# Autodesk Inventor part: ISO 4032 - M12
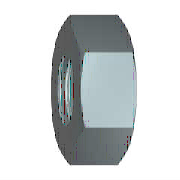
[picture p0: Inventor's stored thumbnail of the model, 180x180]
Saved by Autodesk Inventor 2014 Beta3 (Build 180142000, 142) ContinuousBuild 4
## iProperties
IsCustomPart: 0
Created: 2010-02
Part Number: ISO 4032 - M12
Material: Stainless Steel, 440C
Description: Hexagon nuts, style 1 - Product grades A and B
Document SubType Name: Modeling
Standard: ISO 4032
Designer: Thom Tremblay
Standard Revision: Third edition 1999-08-15
Standards Organization: ISO
Language: en-US
Size Designation: M12
Categories: <MemberInstance><Categories><Category DisplayName="Fasteners" InternalName="e4da775c-781d-43d5-af7c-5136215cf5a6" Mnemonic="FSTN"><Category DisplayName="Nuts" I
Density: 7.75 g/cm^3
Appearance: Steel
Author: Thom Tremblay
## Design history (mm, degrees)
sketch "Sketch1"
  geometry: L1 (-10.392, 0)-(-5.196, 9); L2 (-5.196, 9)-(5.196, 9); L3 (5.196, 9)-(10.392, 0); L4 (10.392, 0)-(5.196, -9); L5 (5.196, -9)-(-5.196, -9); L6 (-5.196, -9)-(-10.392, 0); 2 further points
  constraints: 12 end point, 1 coincident, 1 horizontal, 11 other
  dimensions: "d0" = 20.78461 distance of L3.end L1.start (= 1.1547 x SW)
extrude "Body" new body sketch "Sketch1" distance "d1" = 10.8 (= KOH); taper "d2" = 0 deg
sketch "Sketch2"
  geometry: L1 (0, 5.196)-(0, 10.392) reference; L2 (0, 10.392)-(10.8, 10.392) reference; L3 (10.8, 5.196)-(10.8, 10.392) reference; L4 (-2.16, 0)-(12.96, 0) reference; L5 (1.208, 10.392)-(0, 8.3); L6 (9.592, 10.392)-(10.8, 8.3)
  constraints: 4 end point, 4 point on line
  dimensions: "d3" = 30 deg angle of L1 L5 (= ANG1); "d4" = 30 deg angle of L3 L6 (= ANG2); "d5" = 16.6 diameter of L5.end L4 (= SW0); "d6" = 16.6 diameter of L6.end L4 (= SW01)
revolve "Chamfer1" sketch "Sketch2" stored, may be unused: angle "d7" = 90 deg
sketch "Sketch3"
  geometry: 4 further points
  constraints: 1 coincident, 1 other
hole "Thread" sketch "Sketch3" at (0, 0) diameter "d25" = 10.106; stored, may be unused: countersink angle "d29" = 82 deg, drill point angle "d31" = 118 deg; dims "d26" = 6, "d27" = 4, "d28" = 2, "d30" = 8
workaxis "Work Axis1"
workplane "Work Plane1"
body "Solid1"
chamfer "Chamfer2" distance "d8" = 0.94722 (= -0.5 x GD1 + 0.5 x NND); stored, may be unused: angle "d9" = 30 deg, second distance "d40" = 0.94722 (= -0.5 x GD1 + 0.5 x NND)
chamfer "Chamfer3" distance "d10" = 0.94722 (= -0.5 x GD1 + 0.5 x NND); stored, may be unused: angle "d11" = 30 deg, second distance "d41" = 0.94722 (= -0.5 x GD1 + 0.5 x NND)
other parameters: "ANG1" = 30 deg [user parameter; used in 1 equation term], "ANG2" = 30 deg [user parameter; used in 1 equation term], "NND" = 12 [user parameter; used in 4 equation terms], "KOH" = 10.8 [user parameter; used in 1 equation term], "SW" = 18 [user parameter; used in 2 equation terms], "SW0" = 16.6 [user parameter; used in 2 equation terms], "SW01" = 16.6 (= SW0) [user parameter; used in 1 equation term], "GD1" = 10.10557 (computed from THREADDIA, PTC, TOA) [user parameter; used in 4 equation terms], "d13" = 0, "d14" = 0, "d39" = 0, "d42" = 0, "GUL" = 0.94722 (= 0.541266 x PTC) [user parameter], "TPU" = 5.71429 (computed from PTC) [user parameter], "THREADDIA" = 12 [user parameter; used in 1 equation term], "TOA" = 30 deg [user parameter; used in 1 equation term], "PTC" = 1.75 [user parameter; used in 4 equation terms], "E0" = 20.79 (= 1.155 x SW) [user parameter], "GAL" = 0.94722 (= 0.541266 x PTC) [user parameter]
